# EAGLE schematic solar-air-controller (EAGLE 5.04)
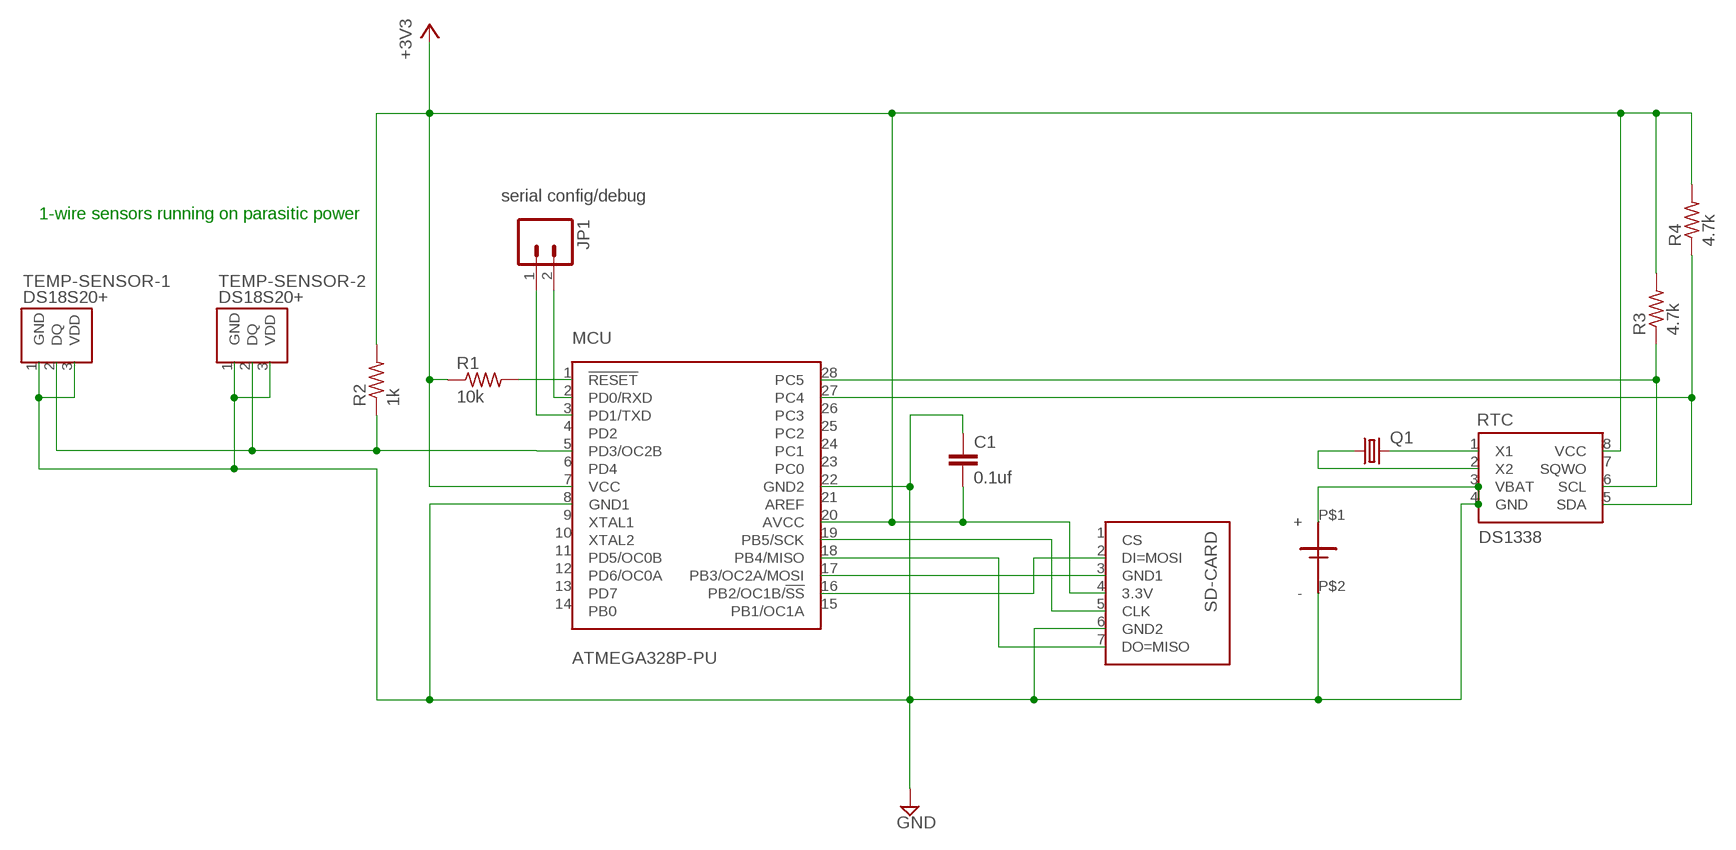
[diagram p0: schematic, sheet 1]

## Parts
C1  0.1uf  C-EU050-024X044  [C050-024X044]
JP1  M02PTH  [1X02]
MCU  ATMEGA328P-PU  [DIL28-3]
Q1  CRYSTALTC26V  [TC26V]
R1  10k  R-US_0309/12  [0309/12]
R2  1k  R-US_0309/12  [0309/12]
R3  4.7k  R-US_0309/12  [0309/12]
R4  4.7k  R-US_0309/12  [0309/12]
RTC  DS1338  [8SOIC]
SD-CARD  SD-CARD-DIY  [7SIL]
TEMP-SENSOR-1  DS18S20+  [3SIL]
TEMP-SENSOR-2  DS18S20+  [3SIL]
U$3  BATTERY-COIN-16MM  [SIL2]

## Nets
+3V3: C1.2 MCU.7(VCC) MCU.20(AVCC) R1.1 R2.2 R3.2 R4.2 RTC.8(VCC) SD-CARD.4(3.3V)
GND: C1.1 MCU.8(GND1) MCU.22(GND2) RTC.3(VBAT) RTC.4(GND) SD-CARD.6(GND2) TEMP-SENSOR-1.1(GND) TEMP-SENSOR-1.3(VDD) TEMP-SENSOR-2.1(GND) TEMP-SENSOR-2.3(VDD) U$3.P$1(+) U$3.P$2(-)
N$1: MCU.5(PD3/OC2B) R2.1 TEMP-SENSOR-1.2(DQ) TEMP-SENSOR-2.2(DQ)
N$2: MCU.1(!RESET) R1.2
N$3: JP1.1 MCU.3(PD1/TXD)
N$4: MCU.17(PB3/OC2A/MOSI) SD-CARD.3(GND1)
N$5: Q1.2 RTC.1(X1)
N$6: Q1.1 RTC.2(X2)
N$7: MCU.28(PC5) R3.1 RTC.6(SCL)
N$8: MCU.27(PC4) R4.1 RTC.5(SDA)
N$9: MCU.19(PB5/SCK) SD-CARD.5(CLK)
N$10: MCU.18(PB4/MISO) SD-CARD.7(DO=MISO)
N$11: MCU.16(PB2/OC1B/!SS) SD-CARD.2(DI=MOSI)
N$12: JP1.2 MCU.2(PD0/RXD)
Unconnected: MCU.4(PD2) MCU.6(PD4) MCU.9(XTAL1) MCU.10(XTAL2) MCU.11(PD5/OC0B) MCU.12(PD6/OC0A) MCU.13(PD7) MCU.14(PB0) MCU.15(PB1/OC1A) MCU.21(AREF) MCU.23(PC0) MCU.24(PC1) MCU.25(PC2) MCU.26(PC3) RTC.7(SQWO) SD-CARD.1(CS)

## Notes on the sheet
- serial config/debug
- 1-wire sensors running on parasitic power

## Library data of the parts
C1 = rcl:C-EU: CAPACITOR, European symbol
JP1 = SparkFun:M02: Header 2
MCU = trl:ATMEGA328P-PU
Q1 = crystal:CRYSTAL: CRYSTAL
R1-R4 = rcl:R-US_: RESISTOR, American symbol
RTC = trl:DS1338
SD-CARD = trl:SD-CARD-DIY
TEMP-SENSOR-1 TEMP-SENSOR-2 = trl:DS18S20+
U$3 = trl:BATTERY-COIN-16MM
